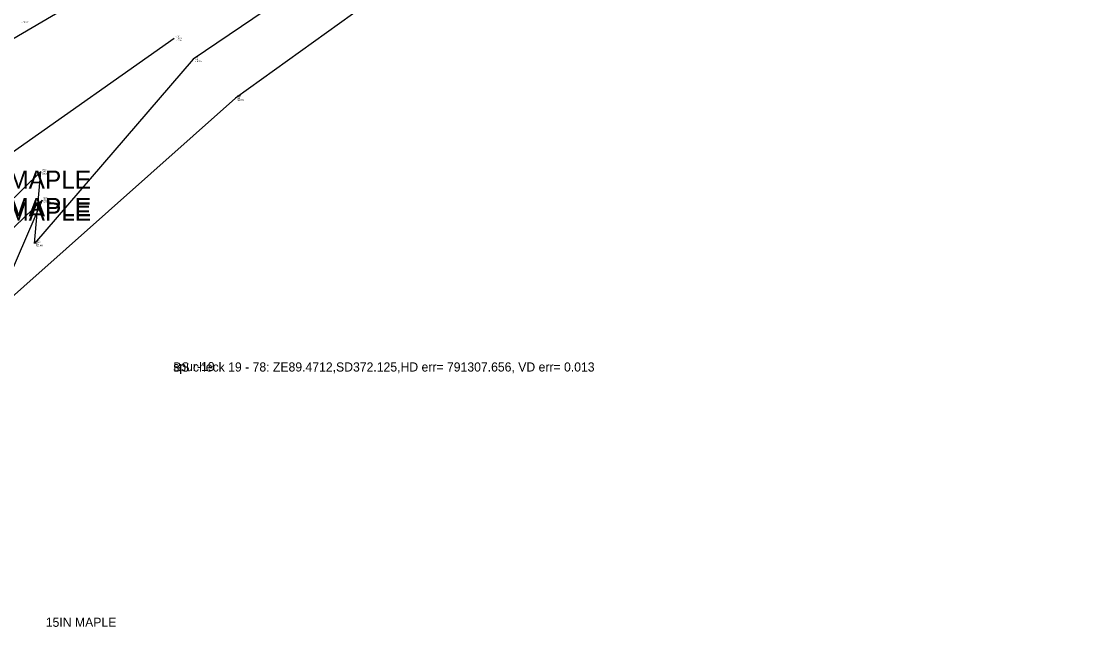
# Model space of a CAD drawing. Extents: x 5447 to 709667, y 4528 to 375505.
# Drawn here: x 704885.5 to 705070.1, y 374884.1 to 374990.3 of the extents above; entities that cross this region are included whole.
import ezdxf

# ---------------------------------------------------------------- set-up
doc = ezdxf.new("R2010")
doc.units = 0
for name, color, linetype in [('SV_BKLN_BKLN', 7, 'Continuous'), ('SV_FENC_FENCES', 7, 'Continuous'), ('SV_NODES_ACTIVE_POINT', 7, 'Continuous'), ('SV_NODES_DESCRIPTION', 7, 'Continuous'), ('SV_NODES_ELEVATION', 7, 'Continuous'), ('SV_NODES_PT_NUMBER', 7, 'Continuous'), ('SV_ROAD_BITRD', 7, 'Continuous'), ('SV_SURVEY_NOTES', 7, 'Continuous'), ('SV_TREE_TREEVEG_TX', 7, 'Continuous'), ('SV_WATR_STREAM', 7, 'Continuous')]:
    doc.layers.add(name, color=color, linetype=linetype)

msp = doc.modelspace()

# ---------------------------------------------------------------- linework, layer by layer
at = {"layer": 'SV_BKLN_BKLN'}
for points in [[(705018.26, 375044.9), (704997.78, 375030.47), (704964.33, 375010.05), (704938.74, 374999.34), (704915.69, 374983.63), (704887.86, 374951.33), (704888.95, 374963.95), (704870.25, 374945.67), (704846.57, 374933.29), (704831.29, 374922.56)], [(704854.22, 374929.54), (704868.35, 374938.91), (704889.19, 374958.96), (704882.05, 374942.42), (704868.07, 374930.98)]]:
    msp.add_lwpolyline(points, dxfattribs=at)
at = {"layer": 'SV_FENC_FENCES'}
msp.add_lwpolyline([(704912.36, 374987.31), (704883.97, 374967.31), (704858.5, 374948.84), (704832.43, 374929.66)], dxfattribs=at)
at = {"layer": 'SV_NODES_ACTIVE_POINT'}
for p, q in [((704912.36, 374987.31), (704912.36, 374987.31)), ((704915.69, 374983.63), (704915.69, 374983.63)), ((704923.06, 374976.82), (704923.06, 374976.82)), ((704888.95, 374963.95), (704888.95, 374963.95)), ((704889.19, 374958.96), (704889.19, 374958.96)), ((704887.86, 374951.33), (704887.86, 374951.33))]:
    msp.add_line(p, q, dxfattribs=at)
at = {"layer": 'SV_ROAD_BITRD'}
msp.add_lwpolyline([(705332.95, 375174.45), (705332.97, 375173.61), (705312, 375173.14), (705281.89, 375169.8), (705259.21, 375164.41), (705223.74, 375156), (705199.49, 375148.17), (705170.62, 375139.39), (705142.92, 375129.01), (705111.15, 375116.86), (705079.95, 375102.83), (705043.66, 375084.18), (705012.65, 375066.5), (704987.08, 375051.13), (704954.3, 375030.35), (704924.01, 375010.66), (704873.84, 374981.22), (704845.83, 374964.24), (704813.68, 374944.49)], dxfattribs=at)
at = {"layer": 'SV_WATR_STREAM'}
msp.add_lwpolyline([(705021.61, 375044.37), (705002.85, 375031.12), (704969.47, 375009.43), (704950.45, 374996.51), (704923.06, 374976.82), (704871.11, 374930.58), (704856.52, 374926.87), (704841.21, 374909.13)], dxfattribs=at)

# ---------------------------------------------------------------- texts
at = {"layer": 'SV_NODES_DESCRIPTION'}
for s, p in [('113 ST', (704912.61, 374987.18)), ('999', (704915.94, 374983.51)), ('118', (704923.31, 374976.7)), ('999', (704889.2, 374963.82)), ('999', (704889.44, 374958.83)), ('999', (704888.11, 374951.21))]:
    msp.add_text(s, height=0.25, dxfattribs=at).set_placement(p)
at = {"layer": 'SV_NODES_ELEVATION'}
for s, p in [('528.231', (704885.61, 374990.04)), ('527.255', (704912.61, 374986.83)), ('526.325', (704915.94, 374983.16)), ('523.879', (704923.31, 374976.35)), ('526.325', (704889.2, 374963.47)), ('524.799', (704889.44, 374958.48)), ('523.463', (704888.11, 374950.86))]:
    msp.add_text(s, height=0.25, dxfattribs=at).set_placement(p)
at = {"layer": 'SV_NODES_PT_NUMBER'}
for s, p in [('5851', (704912.61, 374987.53)), ('5831', (704915.94, 374983.86)), ('5830', (704923.31, 374977.05)), ('5833', (704889.2, 374964.17)), ('5842', (704889.44, 374959.18)), ('5832', (704888.11, 374951.56))]:
    msp.add_text(s, height=0.25, dxfattribs=at).set_placement(p)
at = {"layer": 'SV_SURVEY_NOTES'}
for s, height, p in [('15IN MAPLE', 3.2, (704873.04, 374956.13)), ('15IN MAPLE', 3.2, (704873.04, 374956.13)), ('15IN MAPLE', 3.2, (704873.04, 374956.13)), ('15IN MAPLE', 3.2, (704873.04, 374956.13)), ('15IN MAPLE', 3.2, (704873.04, 374956.13)), ('15IN MAPLE', 3.2, (704873.04, 374956.13)), ('15IN MAPLE', 3.2, (704873.04, 374956.13)), ('15IN MAPLE', 3.2, (704873.04, 374956.13)), ('15IN MAPLE', 3.2, (704873.04, 374955.33)), ('15IN MAPLE', 3.2, (704873.04, 374955.33)), ('15IN MAPLE', 3.2, (704873.04, 374955.33)), ('spur-19', 1.6, (704912.17, 374928.96)), ('spur-19', 1.6, (704912.17, 374928.96)), ('spur-19', 1.6, (704912.17, 374928.96)), ('spur-19', 1.6, (704912.17, 374928.96)), ('spur-19', 1.6, (704912.17, 374928.96)), ('BS check 19 - 78: ZE89.4712,SD372.125,HD err= 791307.656, VD err= 0.013', 1.6, (704912.17, 374928.89)), ('BS check 19 - 78: ZE89.4712,SD372.125,HD err= 791307.656, VD err= 0.013', 1.6, (704912.17, 374928.89)), ('BS check 19 - 78: ZE89.4712,SD372.125,HD err= 791307.656, VD err= 0.013', 1.6, (704912.17, 374928.89)), ('BS check 19 - 78: ZE89.4712,SD372.125,HD err= 791307.656, VD err= 0.013', 1.6, (704912.17, 374928.89)), ('BS check 19 - 78: ZE89.4712,SD372.125,HD err= 791307.656, VD err= 0.013', 1.6, (704912.17, 374928.89)), ('15IN MAPLE', 1.6, (704889.83, 374884.13))]:
    msp.add_text(s, height=height, dxfattribs=at).set_placement(p)
at = {"layer": 'SV_TREE_TREEVEG_TX'}
msp.add_text('15IN MAPLE', height=3.2, dxfattribs=at).set_placement((704873.04, 374960.93))

doc.saveas('drawing.dxf')
